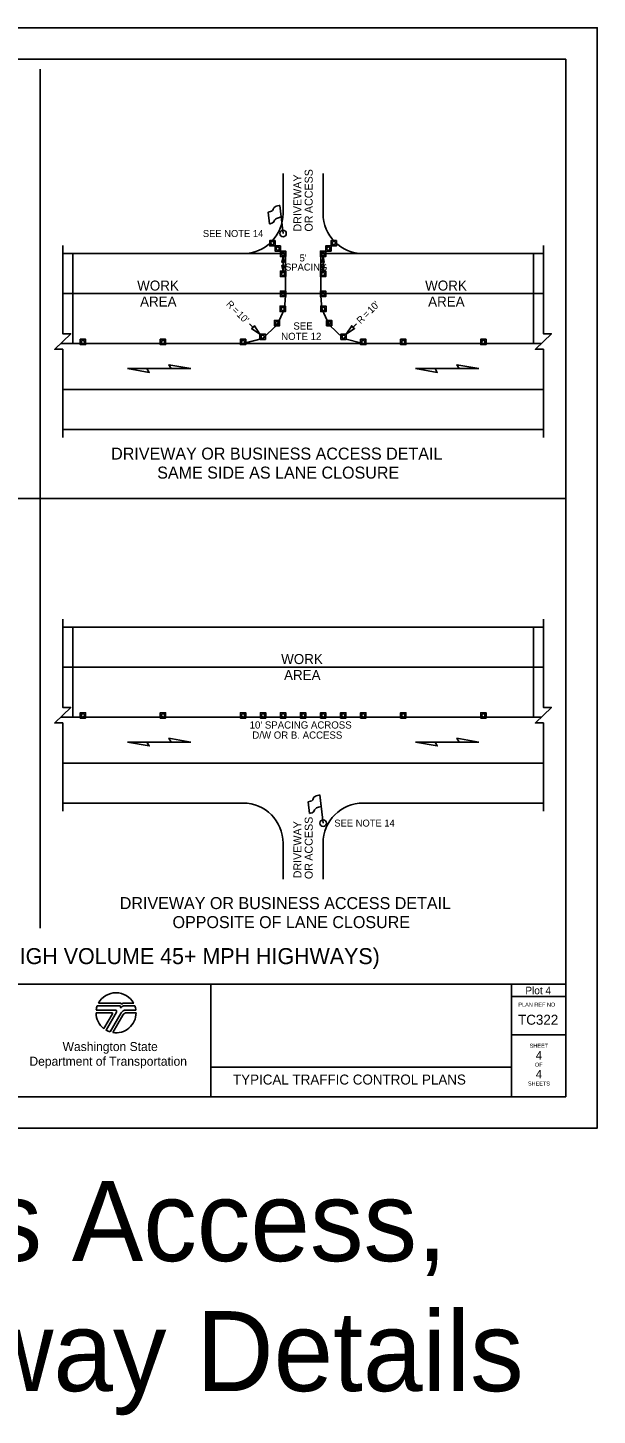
# Model space of a CAD drawing. Extents: x 99999.1 to 100095.7, y 99995 to 100010.7.
# Drawn here: x 100070.38 to 100076.06, y 99996.82 to 100010.69 of the extents above; entities that cross this region are included whole.
import ezdxf

# ---------------------------------------------------------------- set-up
doc = ezdxf.new("R2010")
doc.units = 0
for name, color, linetype in [('RD_ED_DrivewayEdge', 7, 'Continuous'), ('RD_ED_ShoulderPavedEdge', 7, 'Continuous'), ('RD_MK_LineEdgeWhite', 7, 'Continuous'), ('RD_MK_LineSkipCenter', 7, 'Continuous'), ('SH_DE_DetailHeading1Text', 7, 'Continuous'), ('SH_DE_DetailHeading2Text', 7, 'Continuous'), ('SH_GI_PlotLimits', 7, 'Continuous'), ('SH_GI_SheetBorder', 7, 'Continuous'), ('SH_GI_SheetLocationText', 7, 'Continuous'), ('SH_GI_SheetTextInCells', 7, 'Continuous'), ('SH_GI_TitleBlockText', 7, 'Continuous'), ('SH_GI_WSDOTLogo', 7, 'Continuous'), ('TR_WZ_FlaggingStation', 7, 'Continuous'), ('TR_WZ_TrafficCone', 7, 'Continuous'), ('TR_WZ_WorkAreaLabel', 7, 'Continuous'), ('TR_WZ_WorkZoneDetails', 7, 'Continuous'), ('TR_WZ_WorkZoneTextCurrent', 7, 'Continuous')]:
    doc.layers.add(name, color=color, linetype=linetype)

msp = doc.modelspace()

# ---------------------------------------------------------------- linework, layer by layer
at = {"layer": 'RD_ED_DrivewayEdge'}
for p, q in [((100072.925, 100008.83), (100072.925, 100009.23)), ((100073.325, 100008.83), (100073.325, 100009.23)), ((100072.925, 100002.536), (100072.925, 100002.176)), ((100073.325, 100002.536), (100073.325, 100002.176))]:
    msp.add_line(p, q, dxfattribs=at)
for centre, start, end in [((100072.525, 100008.83), 270, 0), ((100073.725, 100008.83), 180, 270), ((100072.525, 100002.536), 0, 90), ((100073.725, 100002.536), 90, 180)]:
    msp.add_arc(centre, 0.4, start, end, dxfattribs=at)
at = {"layer": 'RD_ED_ShoulderPavedEdge'}
for p, q in [((100070.725, 100008.43), (100072.525, 100008.43)), ((100073.725, 100008.43), (100075.525, 100008.43)), ((100070.725, 100006.67), (100075.525, 100006.67)), ((100070.725, 100004.696), (100075.525, 100004.696)), ((100070.725, 100002.936), (100072.525, 100002.936)), ((100073.725, 100002.936), (100075.525, 100002.936))]:
    msp.add_line(p, q, dxfattribs=at)
at = {"layer": 'RD_MK_LineEdgeWhite'}
for p, q in [((100070.725, 100008.03), (100075.525, 100008.03)), ((100070.725, 100007.07), (100075.525, 100007.07)), ((100070.725, 100004.296), (100075.525, 100004.296)), ((100070.725, 100003.336), (100075.525, 100003.336))]:
    msp.add_line(p, q, dxfattribs=at)
at = {"layer": 'RD_MK_LineSkipCenter'}
for points in [[(100075.504, 100007.53), (100070.704, 100007.53)], [(100075.504, 100003.796), (100070.704, 100003.796)]]:
    msp.add_lwpolyline(points, dxfattribs=at)
at = {"layer": 'SH_GI_PlotLimits'}
msp.add_lwpolyline([(100059.062, 99999.687), (100076.062, 99999.687), (100076.062, 100010.687), (100059.062, 100010.687)], close=True, dxfattribs=at)
at = {"layer": 'SH_GI_SheetBorder'}
for p, q in [((100060, 100010.375), (100075.75, 100010.375)), ((100075.75, 100010.375), (100075.75, 100000)), ((100060, 100001.126), (100075.75, 100001.126)), ((100072.205, 100001.126), (100072.205, 100000)), ((100075.208, 100001.126), (100075.208, 100000)), ((100075.208, 100001.001), (100075.75, 100001.001)), ((100075.208, 100000.618), (100075.75, 100000.618)), ((100072.205, 100000.295), (100075.208, 100000.295)), ((100060, 100000), (100075.75, 100000))]:
    msp.add_line(p, q, dxfattribs=at)
at = {"layer": 'SH_GI_WSDOTLogo'}
for p, q in [((100071.059, 100000.866), (100071.25, 100000.866)), ((100071.289, 100000.909), (100071.07, 100000.909)), ((100071.303, 100000.935), (100071.081, 100000.935)), ((100071.433, 100000.935), (100071.335, 100000.935)), ((100071.445, 100000.909), (100071.343, 100000.909)), ((100071.343, 100000.909), (100071.343, 100000.909)), ((100071.356, 100000.866), (100071.456, 100000.866)), ((100071.057, 100000.84), (100071.215, 100000.84)), ((100071.222, 100000.828), (100071.136, 100000.681)), ((100071.261, 100000.846), (100071.157, 100000.667)), ((100071.199, 100000.649), (100071.309, 100000.839)), ((100071.224, 100000.643), (100071.324, 100000.816)), ((100071.365, 100000.839), (100071.457, 100000.839))]:
    msp.add_line(p, q, dxfattribs=at)
for centre, radius, start, end in [((100071.257, 100000.84), 0.2, 28.4787, 151.532), ((100071.257, 100000.84), 0.2, 159.696, 172.5057), ((100071.25, 100000.853), 0.0131, 329.7683, 90), ((100071.289, 100000.895), 0.0148, 327.8418, 89.9985), ((100071.343, 100000.861), 0.0484, 89.9953, 147.8238), ((100071.303, 100000.926), 0.00903, 329.8742, 90.0033), ((100071.356, 100000.812), 0.0542, 90, 149.9974), ((100071.335, 100000.907), 0.0287, 90.0072, 148.1676), ((100071.257, 100000.84), 0.2, 7.4943, 20.2941), ((100071.257, 100000.84), 0.2, 179.9986, 232.8433), ((100071.215, 100000.832), 0.0082, 329.7436, 90), ((100071.257, 100000.84), 0.2, 260.5455, 359.8086), ((100071.365, 100000.792), 0.0476, 90, 150.0543), ((100071.257, 100000.84), 0.2, 239.7929, 253.0448)]:
    msp.add_arc(centre, radius, start, end, dxfattribs=at)
at = {"layer": 'TR_WZ_FlaggingStation'}
for p, q in [((100072.906, 100008.797), (100072.893, 100008.912)), ((100072.925, 100008.63), (100072.893, 100008.911)), ((100072.775, 100008.844), (100072.788, 100008.727)), ((100072.906, 100008.797), (100072.906, 100008.797)), ((100073.175, 100002.949), (100073.188, 100002.832)), ((100073.325, 100002.736), (100073.293, 100003.017)), ((100073.306, 100002.903), (100073.293, 100003.017)), ((100073.306, 100002.903), (100073.306, 100002.903))]:
    msp.add_line(p, q, dxfattribs=at)
for points in [[(100072.893, 100008.912), (100072.887, 100008.91), (100072.869, 100008.907), (100072.856, 100008.903), (100072.846, 100008.897), (100072.837, 100008.892), (100072.832, 100008.885), (100072.827, 100008.877), (100072.827, 100008.871), (100072.821, 100008.862), (100072.811, 100008.854), (100072.798, 100008.849), (100072.775, 100008.844)], [(100072.788, 100008.727), (100072.796, 100008.728), (100072.814, 100008.733), (100072.83, 100008.743), (100072.836, 100008.754), (100072.84, 100008.764), (100072.849, 100008.775), (100072.86, 100008.781), (100072.878, 100008.788), (100072.906, 100008.797)], [(100073.293, 100003.017), (100073.287, 100003.016), (100073.269, 100003.012), (100073.256, 100003.008), (100073.246, 100003.002), (100073.237, 100002.997), (100073.232, 100002.991), (100073.227, 100002.983), (100073.227, 100002.977), (100073.221, 100002.967), (100073.211, 100002.96), (100073.198, 100002.955), (100073.175, 100002.949)], [(100073.188, 100002.832), (100073.196, 100002.834), (100073.214, 100002.838), (100073.23, 100002.849), (100073.236, 100002.859), (100073.24, 100002.87), (100073.249, 100002.88), (100073.26, 100002.887), (100073.278, 100002.894), (100073.306, 100002.903)]]:
    msp.add_lwpolyline(points, dxfattribs=at)
for centre in [(100072.925, 100008.63), (100073.325, 100002.736)]:
    msp.add_circle(centre, 0.0325, dxfattribs=at)
at = {"layer": 'TR_WZ_TrafficCone'}
for points in [[(100072.845, 100008.56), (100072.845, 100008.507), (100072.792, 100008.507), (100072.792, 100008.56), (100072.845, 100008.56)], [(100072.792, 100008.56), (100072.792, 100008.507), (100072.845, 100008.507), (100072.845, 100008.56), (100072.792, 100008.56)], [(100072.898, 100008.507), (100072.898, 100008.454), (100072.845, 100008.454), (100072.845, 100008.507), (100072.898, 100008.507)], [(100072.845, 100008.507), (100072.845, 100008.454), (100072.898, 100008.454), (100072.898, 100008.507), (100072.845, 100008.507)], [(100073.352, 100008.507), (100073.352, 100008.454), (100073.405, 100008.454), (100073.405, 100008.507), (100073.352, 100008.507)], [(100073.405, 100008.507), (100073.405, 100008.454), (100073.352, 100008.454), (100073.352, 100008.507), (100073.405, 100008.507)], [(100073.405, 100008.56), (100073.405, 100008.507), (100073.458, 100008.507), (100073.458, 100008.56), (100073.405, 100008.56)], [(100073.458, 100008.56), (100073.458, 100008.507), (100073.405, 100008.507), (100073.405, 100008.56), (100073.458, 100008.56)], [(100072.898, 100008.454), (100072.952, 100008.454), (100072.952, 100008.4), (100072.898, 100008.4), (100072.898, 100008.454)], [(100072.898, 100008.4), (100072.952, 100008.4), (100072.952, 100008.454), (100072.898, 100008.454), (100072.898, 100008.4)], [(100073.352, 100008.454), (100073.298, 100008.454), (100073.298, 100008.4), (100073.352, 100008.4), (100073.352, 100008.454)], [(100073.352, 100008.4), (100073.298, 100008.4), (100073.298, 100008.454), (100073.352, 100008.454), (100073.352, 100008.4)], [(100072.898, 100008.254), (100072.952, 100008.254), (100072.952, 100008.2), (100072.898, 100008.2), (100072.898, 100008.254)], [(100072.898, 100008.2), (100072.952, 100008.2), (100072.952, 100008.254), (100072.898, 100008.254), (100072.898, 100008.2)], [(100073.352, 100008.254), (100073.298, 100008.254), (100073.298, 100008.2), (100073.352, 100008.2), (100073.352, 100008.254)], [(100073.352, 100008.2), (100073.298, 100008.2), (100073.298, 100008.254), (100073.352, 100008.254), (100073.352, 100008.2)], [(100072.898, 100008.054), (100072.952, 100008.054), (100072.952, 100008), (100072.898, 100008), (100072.898, 100008.054)], [(100072.898, 100008), (100072.952, 100008), (100072.952, 100008.054), (100072.898, 100008.054), (100072.898, 100008)], [(100073.352, 100008.054), (100073.298, 100008.054), (100073.298, 100008), (100073.352, 100008), (100073.352, 100008.054)], [(100073.352, 100008), (100073.298, 100008), (100073.298, 100008.054), (100073.352, 100008.054), (100073.352, 100008)], [(100072.896, 100007.904), (100072.949, 100007.904), (100072.949, 100007.85), (100072.896, 100007.85), (100072.896, 100007.904)], [(100072.896, 100007.85), (100072.949, 100007.85), (100072.949, 100007.904), (100072.896, 100007.904), (100072.896, 100007.85)], [(100073.354, 100007.904), (100073.301, 100007.904), (100073.301, 100007.85), (100073.354, 100007.85), (100073.354, 100007.904)], [(100073.354, 100007.85), (100073.301, 100007.85), (100073.301, 100007.904), (100073.354, 100007.904), (100073.354, 100007.85)], [(100072.838, 100007.762), (100072.891, 100007.762), (100072.891, 100007.708), (100072.838, 100007.708), (100072.838, 100007.762)], [(100072.838, 100007.708), (100072.891, 100007.708), (100072.891, 100007.762), (100072.838, 100007.762), (100072.838, 100007.708)], [(100073.412, 100007.762), (100073.359, 100007.762), (100073.359, 100007.708), (100073.412, 100007.708), (100073.412, 100007.762)], [(100073.412, 100007.708), (100073.359, 100007.708), (100073.359, 100007.762), (100073.412, 100007.762), (100073.412, 100007.708)], [(100070.899, 100007.574), (100070.952, 100007.574), (100070.952, 100007.52), (100070.899, 100007.52), (100070.899, 100007.574)], [(100070.899, 100007.52), (100070.952, 100007.52), (100070.952, 100007.574), (100070.899, 100007.574), (100070.899, 100007.52)], [(100071.699, 100007.574), (100071.752, 100007.574), (100071.752, 100007.52), (100071.699, 100007.52), (100071.699, 100007.574)], [(100071.699, 100007.52), (100071.752, 100007.52), (100071.752, 100007.574), (100071.699, 100007.574), (100071.699, 100007.52)], [(100072.499, 100007.574), (100072.552, 100007.574), (100072.552, 100007.52), (100072.499, 100007.52), (100072.499, 100007.574)], [(100072.499, 100007.52), (100072.552, 100007.52), (100072.552, 100007.574), (100072.499, 100007.574), (100072.499, 100007.52)], [(100072.694, 100007.625), (100072.748, 100007.625), (100072.748, 100007.571), (100072.694, 100007.571), (100072.694, 100007.625)], [(100072.694, 100007.571), (100072.748, 100007.571), (100072.748, 100007.625), (100072.694, 100007.625), (100072.694, 100007.571)], [(100073.556, 100007.625), (100073.502, 100007.625), (100073.502, 100007.571), (100073.556, 100007.571), (100073.556, 100007.625)], [(100073.556, 100007.571), (100073.502, 100007.571), (100073.502, 100007.625), (100073.556, 100007.625), (100073.556, 100007.571)], [(100073.699, 100007.574), (100073.752, 100007.574), (100073.752, 100007.52), (100073.699, 100007.52), (100073.699, 100007.574)], [(100073.699, 100007.52), (100073.752, 100007.52), (100073.752, 100007.574), (100073.699, 100007.574), (100073.699, 100007.52)], [(100074.099, 100007.574), (100074.152, 100007.574), (100074.152, 100007.52), (100074.099, 100007.52), (100074.099, 100007.574)], [(100074.099, 100007.52), (100074.152, 100007.52), (100074.152, 100007.574), (100074.099, 100007.574), (100074.099, 100007.52)], [(100074.899, 100007.574), (100074.952, 100007.574), (100074.952, 100007.52), (100074.899, 100007.52), (100074.899, 100007.574)], [(100074.899, 100007.52), (100074.952, 100007.52), (100074.952, 100007.574), (100074.899, 100007.574), (100074.899, 100007.52)], [(100070.899, 100003.839), (100070.952, 100003.839), (100070.952, 100003.786), (100070.899, 100003.786), (100070.899, 100003.839)], [(100070.899, 100003.786), (100070.952, 100003.786), (100070.952, 100003.839), (100070.899, 100003.839), (100070.899, 100003.786)], [(100071.699, 100003.839), (100071.752, 100003.839), (100071.752, 100003.786), (100071.699, 100003.786), (100071.699, 100003.839)], [(100071.699, 100003.786), (100071.752, 100003.786), (100071.752, 100003.839), (100071.699, 100003.839), (100071.699, 100003.786)], [(100072.499, 100003.839), (100072.552, 100003.839), (100072.552, 100003.786), (100072.499, 100003.786), (100072.499, 100003.839)], [(100072.499, 100003.786), (100072.552, 100003.786), (100072.552, 100003.839), (100072.499, 100003.839), (100072.499, 100003.786)], [(100072.699, 100003.839), (100072.752, 100003.839), (100072.752, 100003.786), (100072.699, 100003.786), (100072.699, 100003.839)], [(100072.699, 100003.786), (100072.752, 100003.786), (100072.752, 100003.839), (100072.699, 100003.839), (100072.699, 100003.786)], [(100072.899, 100003.839), (100072.952, 100003.839), (100072.952, 100003.786), (100072.899, 100003.786), (100072.899, 100003.839)], [(100072.899, 100003.786), (100072.952, 100003.786), (100072.952, 100003.839), (100072.899, 100003.839), (100072.899, 100003.786)], [(100073.099, 100003.839), (100073.152, 100003.839), (100073.152, 100003.786), (100073.099, 100003.786), (100073.099, 100003.839)], [(100073.099, 100003.786), (100073.152, 100003.786), (100073.152, 100003.839), (100073.099, 100003.839), (100073.099, 100003.786)], [(100073.299, 100003.839), (100073.352, 100003.839), (100073.352, 100003.786), (100073.299, 100003.786), (100073.299, 100003.839)], [(100073.299, 100003.786), (100073.352, 100003.786), (100073.352, 100003.839), (100073.299, 100003.839), (100073.299, 100003.786)], [(100073.499, 100003.839), (100073.552, 100003.839), (100073.552, 100003.786), (100073.499, 100003.786), (100073.499, 100003.839)], [(100073.499, 100003.786), (100073.552, 100003.786), (100073.552, 100003.839), (100073.499, 100003.839), (100073.499, 100003.786)], [(100073.699, 100003.839), (100073.752, 100003.839), (100073.752, 100003.786), (100073.699, 100003.786), (100073.699, 100003.839)], [(100073.699, 100003.786), (100073.752, 100003.786), (100073.752, 100003.839), (100073.699, 100003.839), (100073.699, 100003.786)], [(100074.099, 100003.839), (100074.152, 100003.839), (100074.152, 100003.786), (100074.099, 100003.786), (100074.099, 100003.839)], [(100074.099, 100003.786), (100074.152, 100003.786), (100074.152, 100003.839), (100074.099, 100003.839), (100074.099, 100003.786)], [(100074.899, 100003.839), (100074.952, 100003.839), (100074.952, 100003.786), (100074.899, 100003.786), (100074.899, 100003.839)], [(100074.899, 100003.786), (100074.952, 100003.786), (100074.952, 100003.839), (100074.899, 100003.839), (100074.899, 100003.786)]]:
    msp.add_lwpolyline(points, dxfattribs=at)
for centre in [(100072.818, 100008.534), (100072.872, 100008.48), (100073.378, 100008.48), (100073.432, 100008.534), (100072.925, 100008.427), (100073.325, 100008.427), (100072.925, 100008.227), (100073.325, 100008.227), (100072.925, 100008.027), (100073.325, 100008.027), (100072.922, 100007.877), (100073.328, 100007.877), (100072.865, 100007.735), (100073.385, 100007.735), (100070.926, 100007.547), (100071.726, 100007.547), (100072.526, 100007.547), (100072.721, 100007.598), (100073.529, 100007.598), (100073.726, 100007.547), (100074.126, 100007.547), (100074.926, 100007.547), (100070.926, 100003.813), (100071.726, 100003.813), (100072.526, 100003.813), (100072.726, 100003.813), (100072.926, 100003.813), (100073.126, 100003.813), (100073.326, 100003.813), (100073.526, 100003.813), (100073.726, 100003.813), (100074.126, 100003.813), (100074.926, 100003.813)]:
    msp.add_circle(centre, 0.0167, dxfattribs=at)
at = {"layer": 'TR_WZ_WorkZoneDetails'}
for p, q in [((100070.5, 100010.275), (100070.5, 100001.686)), ((100072.925, 100008.346), (100072.925, 100008.308)), ((100073.325, 100008.346), (100073.325, 100008.308)), ((100072.628, 100007.691), (100072.59, 100007.729)), ((100073.622, 100007.691), (100073.66, 100007.729)), ((100071.566, 100007.28), (100071.808, 100007.28)), ((100071.808, 100007.28), (100071.566, 100007.28)), ((100074.443, 100007.28), (100074.684, 100007.28)), ((100074.684, 100007.28), (100074.443, 100007.28)), ((100070.5, 100005.98), (100065.25, 100005.98)), ((100075.75, 100005.98), (100070.5, 100005.98)), ((100071.566, 100003.546), (100071.808, 100003.546)), ((100071.808, 100003.546), (100071.566, 100003.546)), ((100074.443, 100003.546), (100074.684, 100003.546)), ((100074.684, 100003.546), (100074.443, 100003.546))]:
    msp.add_line(p, q, dxfattribs=at)
for points in [[(100070.725, 100006.59), (100070.725, 100007.473), (100070.645, 100007.473), (100070.805, 100007.628), (100070.725, 100007.628), (100070.725, 100008.51)], [(100075.525, 100006.59), (100075.525, 100007.473), (100075.445, 100007.473), (100075.605, 100007.628), (100075.525, 100007.628), (100075.525, 100008.51)], [(100070.725, 100002.856), (100070.725, 100003.738), (100070.645, 100003.738), (100070.805, 100003.893), (100070.725, 100003.893), (100070.725, 100004.776)], [(100075.525, 100002.856), (100075.525, 100003.738), (100075.445, 100003.738), (100075.605, 100003.893), (100075.525, 100003.893), (100075.525, 100004.776)]]:
    msp.add_lwpolyline(points, dxfattribs=at)
for points in [[(100072.948, 100008.43), (100072.948, 100008.207), (100072.948, 100008.007), (100072.939, 100007.877), (100072.939, 100007.877), (100072.939, 100007.877), (100072.865, 100007.718), (100072.865, 100007.718), (100072.865, 100007.718), (100072.721, 100007.581), (100072.526, 100007.53), (100071.529, 100007.53), (100070.949, 100007.53), (100070.825, 100007.53), (100070.825, 100008.43)], [(100072.925, 100008.4), (100072.936, 100008.343), (100072.925, 100008.346), (100072.914, 100008.343)], [(100075.425, 100008.43), (100075.425, 100008.03), (100075.425, 100007.53), (100074.501, 100007.53), (100074.501, 100007.53), (100074.501, 100007.53), (100073.726, 100007.53), (100073.726, 100007.53), (100073.726, 100007.53), (100073.529, 100007.581), (100073.385, 100007.718), (100073.311, 100007.877), (100073.302, 100008.007), (100073.302, 100008.207), (100073.302, 100008.43)], [(100073.325, 100008.4), (100073.336, 100008.343), (100073.325, 100008.346), (100073.314, 100008.343)], [(100072.925, 100008.254), (100072.936, 100008.311), (100072.925, 100008.308), (100072.914, 100008.311)], [(100073.325, 100008.254), (100073.336, 100008.311), (100073.325, 100008.308), (100073.314, 100008.311)], [(100072.694, 100007.625), (100072.611, 100007.681), (100072.628, 100007.691), (100072.639, 100007.708)], [(100073.556, 100007.625), (100073.639, 100007.681), (100073.622, 100007.691), (100073.611, 100007.708)], [(100071.37, 100007.28), (100071.589, 100007.242), (100071.566, 100007.28)], [(100072.004, 100007.28), (100071.785, 100007.319), (100071.808, 100007.28)], [(100074.247, 100007.28), (100074.465, 100007.242), (100074.443, 100007.28)], [(100074.881, 100007.28), (100074.662, 100007.319), (100074.684, 100007.28)], [(100070.825, 100004.696), (100070.825, 100003.796), (100075.425, 100003.796), (100075.425, 100004.696)], [(100071.37, 100003.546), (100071.589, 100003.507), (100071.566, 100003.546)], [(100072.004, 100003.546), (100071.785, 100003.584), (100071.808, 100003.546)], [(100074.247, 100003.546), (100074.465, 100003.507), (100074.443, 100003.546)], [(100074.881, 100003.546), (100074.662, 100003.584), (100074.684, 100003.546)]]:
    msp.add_lwpolyline(points, close=True, dxfattribs=at)

# ---------------------------------------------------------------- texts
at = {"layer": 'SH_DE_DetailHeading1Text'}
msp.add_text('ALTERNATING 1-LANE, 2-WAY TRAFFIC: FLAGGER-CONTROLLED + TEMP. RUMBLE STRIPS (HIGH VOLUME 45+ MPH HIGHWAYS)', height=0.16, rotation=360, dxfattribs=at).set_placement((100060.588, 100001.326))
at = {"layer": 'SH_DE_DetailHeading2Text'}
for s, p in [('DRIVEWAY OR BUSINESS ACCESS DETAIL', (100071.208, 100006.37)), ('SAME SIDE AS LANE CLOSURE', (100071.668, 100006.18)), ('DRIVEWAY OR BUSINESS ACCESS DETAIL', (100071.294, 100001.876)), ('OPPOSITE OF LANE CLOSURE', (100071.821, 100001.686))]:
    msp.add_text(s, height=0.12, rotation=360, dxfattribs=at).set_placement(p)
at = {"layer": 'SH_GI_SheetBorder'}
msp.add_text('PLAN REF NO', height=0.04003, dxfattribs=at).set_placement((100075.275, 100000.901))
at = {"layer": 'SH_GI_SheetLocationText'}
for s, height, p in [('Plot 4', 0.075, (100075.345, 100001.025)), ('Driveway, Business Access,', 0.8, (100061.184, 99998.357)), ('or Intersecting Roadway Details', 0.8, (100060.225, 99997.057))]:
    msp.add_text(s, height=height, dxfattribs=at).set_placement(p)
at = {"layer": 'SH_GI_SheetTextInCells'}
for s, height, p in [('Washington State', 0.09007, (100070.723, 100000.457)), ('SHEET', 0.04, (100075.388, 100000.49)), ('Department of Transportation', 0.09007, (100070.392, 100000.31)), ('OF', 0.04, (100075.441, 100000.301)), ('SHEETS', 0.04, (100075.37, 100000.112))]:
    msp.add_text(s, height=height, dxfattribs=at).set_placement(p)
at = {"layer": 'SH_GI_TitleBlockText'}
for s, height, p in [('TC322', 0.1, (100075.272, 100000.72)), ('4', 0.085, (100075.449, 100000.372)), ('TYPICAL TRAFFIC CONTROL PLANS', 0.1, (100072.425, 100000.122)), ('4', 0.085, (100075.449, 100000.184))]:
    msp.add_text(s, height=height, dxfattribs=at).set_placement(p)
at = {"layer": 'TR_WZ_WorkAreaLabel'}
for s, p in [('WORK', (100071.468, 100008.06)), ('WORK', (100074.344, 100008.06)), ('AREA', (100071.497, 100007.9)), ('AREA', (100074.374, 100007.9)), ('WORK', (100072.906, 100004.326)), ('AREA', (100072.935, 100004.166))]:
    msp.add_text(s, height=0.1, dxfattribs=at).set_placement(p)
at = {"layer": 'TR_WZ_WorkZoneTextCurrent'}
for s, height, rotation, p in [('DRIVEWAY', 0.08, 90, (100073.109, 100008.65)), ('ACCESS', 0.08, 90, (100073.221, 100008.834)), ('OR', 0.08, 90, (100073.221, 100008.65)), ('R', 0.07, 315, (100072.351, 100007.919)), ("10'", 0.07, 45, (100073.808, 100007.827)), ('=', 0.07, 315, (100072.41, 100007.859)), ("10'", 0.07, 315, (100072.457, 100007.813)), ('R', 0.07, 45, (100073.701, 100007.721)), ('=', 0.07, 45, (100073.761, 100007.78)), ('ACCESS', 0.08, 90, (100073.221, 100002.36)), ('DRIVEWAY', 0.08, 90, (100073.109, 100002.184)), ('OR', 0.08, 90, (100073.221, 100002.176))]:
    msp.add_text(s, height=height, rotation=rotation, dxfattribs=at).set_placement(p)
for s, height, p in [('SEE NOTE 14', 0.07, (100072.124, 100008.595)), ("5'", 0.07, (100073.09, 100008.351)), ('SPACING', 0.07, (100072.945, 100008.26)), ('SEE', 0.072, (100073.028, 100007.67)), ('NOTE 12', 0.072, (100072.906, 100007.566)), ("10' SPACING ACROSS", 0.072, (100072.591, 100003.681)), ('D/W OR B. ACCESS', 0.072, (100072.618, 100003.58)), ('SEE NOTE 14', 0.07, (100073.437, 100002.701))]:
    msp.add_text(s, height=height, dxfattribs=at).set_placement(p)

doc.saveas('drawing.dxf')
